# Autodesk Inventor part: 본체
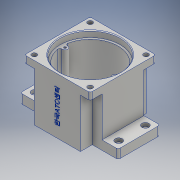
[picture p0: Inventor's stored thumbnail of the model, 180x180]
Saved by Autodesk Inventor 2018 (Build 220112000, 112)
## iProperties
Created: 2020-07
Part Number: 본체
Material: 알루미늄 6061
Document SubType Name: Modeling
Designer: Admin
Density: 2.7 g/cm^3
Appearance: 알루미늄 - 평지
Author: Admin
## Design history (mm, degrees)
sketch "스케치1"
  geometry: L1 (-98, 0)-(98, 0) reference; L2 (0, -65.8)-(0, 65.8) reference; L3 (-70, 0)-(-70, 30); L4 (-70, 30)-(-33, 30); L5 (-33, 30)-(-33, 47); L6 (-33, 47)-(0, 47); L7 (98, 0)-(-98, 0); L8 (70, 0)-(70, 30); L9 (70, 30)-(33, 30); L10 (33, 30)-(33, 47); L11 (33, 47)-(0, 47); L12 (0, 65.8)-(0, -65.8); L13 (-70, 0)-(-70, -30); L14 (-70, -30)-(-33, -30); L15 (-33, -30)-(-33, -47); L16 (-33, -47)-(0, -47); L17 (70, 0)-(70, -30); L18 (70, -30)-(33, -30); L19 (33, -30)-(33, -47); L20 (33, -47)-(0, -47); 1 further point
  constraints: 36 end point, 15 symmetric about line, 4 point on line, 3 perpendicular, 1 vertical
  dimensions: "d0" = 66 distance between parallel lines of L10 L5; "d1" = 140 distance between parallel lines of L17 L13; "d2" = 60 distance between parallel lines of L18 L9; "d3" = 94 distance between parallel lines of L20 L11
extrude "돌출1" new body sketch "스케치1" distance "d4" = 13; taper "d5" = 0 deg
sketch "스케치2"
  geometry: 1 further point
sketch "스케치3"
  geometry: L1 (33, 47)-(33, 30) reference; L2 (-33, -47)-(33, -47); L3 (33, -47)-(33, 47); L4 (33, 47)-(-33, 47); L5 (-33, 47)-(-33, -47); L6 (-33, -47)-(33, 47); L7 (33, -47)-(-33, 47); L8 (33, 30)-(70, 30) reference; L9 (33, -30)-(70, -30) reference; L10 (33, 30)-(47, 30); L11 (47, 30)-(47, -30); L12 (47, -30)-(33, -30); L13 (33, -30)-(33, 30); L14 (0, -65.8)-(0, 65.8) reference; L15 (-33, 47)-(-33, 30); L16 (33, -47)-(-33, -47); L17 (-33, -47)-(-33, 47); L18 (-33, -47)-(33, 47); L19 (-33, 30)-(-47, 30); L20 (-33, -30)-(-47, -30); L21 (-33, 30)-(-47, 30); L22 (-47, 30)-(-47, -30); L23 (-47, -30)-(-33, -30); L24 (-33, -30)-(-33, 30); 3 further points
  constraints: 40 end point, 11 symmetric about line, 4 parallel, 2 horizontal, 2 midpoint, 2 perpendicular, 1 point on line
  dimensions: "d6" = 14 distance between parallel lines of L3 L11
extrude "돌출2" join sketch "스케치3" distance "d7" = 57; taper "d8" = 0 deg
sketch "스케치4"
  geometry: L1 (-47, -47)-(47, -47); L2 (47, -47)-(47, 47); L3 (47, 47)-(-47, 47); L4 (-47, 47)-(-47, -47); L5 (-47, -47)-(47, 47); L6 (47, -47)-(-47, 47); 1 further point
  constraints: 12 end point, 2 midpoint, 2 parallel, 1 horizontal, 1 perpendicular
  dimensions: "d9" = 94 distance of L3.end L2.end; "d10" = 94 distance of L1.end L2.end
extrude "돌출3" join sketch "스케치4" distance "d11" = 10; taper "d12" = 0 deg
sketch "스케치5"
  geometry: L1 (98, 0)-(-98, 0) reference; L2 (0, -65.8)-(0, 65.8) reference; C1 r 27.5 at (0, -11); 1 further point
  constraints: 1 centre point, 1 point on line
  dimensions: "d13" = 55 diameter of C1; "d14" = 11 distance from line of L1 C1.centre
extrude "돌출4" join sketch "스케치5" distance "d15" = 7; taper "d16" = 0 deg
sketch "스케치6"
  geometry: C1 r 43 at (0, 0); 1 further point
  constraints: 1 centre point, 1 coincident
  dimensions: "d17" = 86 diameter of C1
extrude "돌출5" cut sketch "스케치6" distance "d18" = 9; taper "d19" = 0 deg
sketch "스케치7" dims "d22" = 72
  geometry: L1 (0, -65.8)-(0, 65.8) reference; L2 (-137.2, 0)-(137.2, 0) reference; L3 (137.2, 0)-(-137.2, 0); C1 r 43 at (0, 0); A1 r 40 centre (0, 0) between (39.29, 7.503) and (-39.29, 7.503); A2 r 4 centre (36, 0) between (36.615, 3.952) and (36.615, -3.952); A3 r 3 centre (36.343, -6.94) between (39.29, -7.503) and (35.778, -3.994); A4 r 3 centre (36.343, 6.94) between (35.778, 3.994) and (39.29, 7.503); A5 r 4 centre (-36, 0) between (-36.615, -3.952) and (-36.615, 3.952); A6 r 3 centre (-36.343, -6.94) between (-35.778, -3.994) and (-39.29, -7.503); A7 r 3 centre (-36.343, 6.94) between (-39.29, 7.503) and (-35.778, 3.994); A8 r 40 centre (0, 0) between (-39.29, -7.503) and (39.29, -7.503); A9 r 40 centre (0, 0) between (-39.29, 7.503) and (-39.29, -7.503); 2 further points
  constraints: 24 point on circle, 14 symmetric about line, 10 centre point, 3 coincident, 2 end point, 2 point on line, 2 tangent, 1 vertical, 10 other
  dimensions: "d20" = 80 diameter of A1; "d21" = 86 diameter of C1; "d23" = 8 diameter of A2; "d24" = 3 radius of A3
extrude "돌출6" cut sketch "스케치7" distance "d25" = 62; taper "d26" = 0 deg
sketch "스케치8"
  geometry: L1 (0, -65.8)-(0, 65.8) reference; L2 (-98, 0)-(98, 0) reference; C1 r 21 at (0, -11); C2 r 15 at (0, 20); 1 further point
  constraints: 2 centre point, 2 point on line
  dimensions: "d27" = 42 diameter of C1; "d28" = 30 diameter of C2; "d29" = 11 distance from line of L2 C1.centre; "d30" = 20 distance from line of L2 C2.centre
extrude "돌출7" join sketch "스케치8" distance "d31" = 7; taper "d32" = 0 deg
sketch "스케치9"
  geometry: C1 r 17.5 at (0, -11); A1 r 21 centre (0, -11) between (-8.978, 7.984) and (8.978, 7.984) reference; A2 r 15 centre (0, 20) between (8.978, 7.984) and (-8.978, 7.984) reference; 1 further point
  constraints: 1 centre point, 1 coincident
  dimensions: "d33" = 35 diameter of C1
extrude "돌출8" cut sketch "스케치9" distance "d34" = 10; taper "d35" = 0 deg
sketch "스케치10"
  geometry: C1 r 17.5 at (0, 0) reference; C2 r 12.5 at (0, 0); 1 further point
  constraints: 1 centre point, 1 coincident
  dimensions: "d36" = 25 diameter of C2
extrude "돌출9" cut sketch "스케치10" distance "d37" = 4.7; taper "d38" = 0 deg
sketch "스케치11"
  geometry: C1 r 12.5 at (0, 0) reference; C2 r 16 at (0, 0); 1 further point
  constraints: 1 centre point, 1 coincident
  dimensions: "d39" = 32 diameter of C2
extrude "돌출10" cut sketch "스케치11" distance "d40" = 8.3; taper "d41" = 0 deg
sketch "스케치12"
  geometry: C1 r 17.5 at (0, -11) reference; C2 r 11 at (0, 20); A1 r 21 centre (0, -11) between (-8.978, 7.984) and (8.978, 7.984) reference; A2 r 15 centre (0, 20) between (8.978, 7.984) and (-8.978, 7.984) reference; 1 further point
  constraints: 1 centre point, 1 coincident
  dimensions: "d42" = 22 diameter of C2
extrude "돌출11" cut sketch "스케치12" distance "d43" = 7; taper "d44" = 0 deg
sketch "스케치13"
  geometry: C1 r 27.5 at (0, -31) reference; C2 r 11 at (0, 0) reference; C3 r 9.5 at (0, 0); 1 further point
  constraints: 1 centre point, 1 coincident
  dimensions: "d45" = 19 diameter of C3
extrude "돌출12" cut sketch "스케치13" distance "d46" = 3; taper "d47" = 0 deg
sketch "스케치15"
  geometry: L1 (47, 30)-(47, -30) reference; L2 (47, -30)-(70, -30) reference; L3 (70, -30)-(70, 30) reference; L4 (70, 30)-(47, 30) reference; L5 (0, -65.8)-(0, 65.8) reference; L6 (-98, 0)-(98, 0) reference; 3 further points
  dimensions: "d52" = 11 distance from line of L4 point (60, 19); "d53" = 10 distance from line of L3 point (60, 19); "d54" = 10 distance from line of L3 point (60, -19); "d55" = 11 distance from line of L2 point (60, -19)
hole "구멍1" sketch "스케치15" at (60, 19), (60, -19) diameter "d56" = 4.5; stored, may be unused: countersink angle "d60" = 90 deg, drill point angle "d62" = 0 deg; dims "d57" = 6, "d58" = 10, "d59" = 5, "d61" = 8
sketch "스케치16"
  geometry: C1 r 43 at (0, 0) reference; A1 r 4 centre (36, 0) between (36.615, 3.952) and (36.615, -3.952) reference; A2 r 3 centre (36.343, -6.94) between (39.29, -7.503) and (36.615, -3.952) reference; A3 r 40 centre (0, 0) between (-39.29, -7.503) and (39.29, -7.503) reference; A4 r 3 centre (-36.343, -6.94) between (-36.615, -3.952) and (-39.29, -7.503) reference; A5 r 4 centre (-36, 0) between (-36.615, -3.952) and (-36.615, 3.952) reference; A6 r 3 centre (-36.343, 6.94) between (-39.29, 7.503) and (-36.615, 3.952) reference; A7 r 40 centre (0, 0) between (39.29, 7.503) and (-39.29, 7.503) reference; A8 r 3 centre (36.343, 6.94) between (36.615, 3.952) and (39.29, 7.503) reference; 3 further points
  constraints: 2 coincident
hole "구멍2" sketch "스케치16" at (36, 0), (-36, 0) diameter "d63" = 3.242; stored, may be unused: countersink angle "d67" = 90 deg, drill point angle "d69" = 118 deg; dims "d64" = 7, "d65" = 10, "d66" = 5, "d68" = 9
fillet "모깎기1" dims "d70" = 3
sketch "스케치18"
  geometry: L1 (-47, 44)-(-47, -44) reference; L2 (-44, -47)-(44, -47) reference; L3 (47, -44)-(47, 44) reference; L4 (44, 47)-(-44, 47) reference; L5 (0, -66.67)-(0, 66.67) reference; L6 (-98, 0)-(98, 0) reference; C1 r 43 at (0, 0) reference; A1 r 3 centre (-44, 44) between (-44, 47) and (-47, 44) reference; A2 r 3 centre (-44, -44) between (-47, -44) and (-44, -47) reference; A3 r 3 centre (44, -44) between (44, -47) and (47, -44) reference; A4 r 3 centre (44, 44) between (47, 44) and (44, 47) reference; 5 further points
  dimensions: "d71" = 7 distance from line of L3 point (40, -40); "d72" = 7 distance from line of L1 point (-40, -40); "d73" = 7 distance from line of L3 point (40, 40); "d74" = 7 distance from line of L1 point (-40, 40); "d75" = 7 distance from line of L2 point (40, -40); "d76" = 7 distance from line of L2 point (-40, -40); "d77" = 7 distance from line of L4 point (-40, 40); "d78" = 7 distance from line of L4 point (40, 40)
hole "구멍3" sketch "스케치18" at (40, -40), (-40, -40), (-40, 40), (40, 40) diameter "d79" = 7; stored, may be unused: countersink angle "d83" = 90 deg, drill point angle "d85" = 0 deg; dims "d80" = 7, "d81" = 10, "d82" = 5, "d84" = 10
sketch "스케치19"
  geometry: L1 (-11, 80)-(77, 80) reference; L2 (66, 0)-(0, 0) reference; 3 further points
  constraints: 1 midpoint, 1 vertical alignment, 1 other
  dimensions: "d86" = 40 distance from line of L1 point (33, 40)
feature "엠보싱1" sketch "스케치19" dims "d0" = 66, "d1" = 140, "d2" = 60, "d3" = 94, "d87" = 0.5, "d88" = 0
fillet "모깎기2" dims "d89" = 3
chamfer "모따기1" distance "d90" = 0.8; stored, may be unused: second distance "d91" = 2, angle "d92" = 30 deg
chamfer "모따기2" distance "d93" = 1; stored, may be unused: second distance "d94" = 2, angle "d95" = 30 deg
fillet "모깎기3" dims "d96" = 3
chamfer "모따기3" distance "d97" = 1; stored, may be unused: second distance "d98" = 2, angle "d99" = 30 deg
node "솔리드1"
mirror "미러1"
node "투영된 루프1"
node "투영된 루프2"
node "투영된 루프3"
node "투영된 루프4"
node "투영된 루프5"
node "투영된 루프7"
node "투영된 루프8"
node "투영된 루프9"
